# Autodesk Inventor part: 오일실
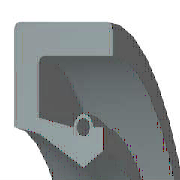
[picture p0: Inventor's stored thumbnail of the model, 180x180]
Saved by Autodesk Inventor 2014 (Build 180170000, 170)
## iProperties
IsCustomPart: 1
Created: 2015-12
Part Number: 오일실
Material: 일반
Description: 오일-실
Document SubType Name: Modeling
Standard: KS B 2804
Designer: mdu
Standards Organization: KS
Language: ko-KR
Size Designation: S - 15 30 7
Categories: <MemberInstance><Categories><Category DisplayName="샤프트 부품" InternalName="7f7aeb1f-a693-4053-b835-cee3144e0d98" Mnemonic="SHFT"><Category DisplayName="실링" Intern
Density: 1 g/cm^3
Appearance: 기본값
Mass: 1.76736 g
Surface Area: 26.6454 cm^2
Volume: 1.76736 cm^3
Author: mdu
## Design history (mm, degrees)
revolve "본체" stored, may be unused: angle "d17" = 90 deg
revolve "스프링1" stored, may be unused: angle "d18" = 90 deg
body "Solid1"
sketch "스케치1"
  geometry: L1 (0, 15)-(7, 15); L2 (7, 15)-(7, 13.75); L3 (7, 13.75)-(1.75, 13.75); L4 (0, 15)-(0, 9.6); L5 (0, 9.6)-(1.75, 9.25); L6 (1.75, 9.25)-(4.9, 7.5); L7 (4.9, 7.5)-(0, 7.5); L8 (6.3, 8.375)-(6.3, 9.6); L9 (0, 0)-(9.586, 0) reference; L10 (4.9, 7.5)-(6.3, 8.375); L11 (0, 18)-(0, -3) reference; L12 (-1.917, 0)-(11.503, 0) reference; L13 (4.2, 9.6)-(1.75, 10.09); L14 (1.75, 10.09)-(1.75, 13.75); L15 (6.3, 9.6)-(5.6, 9.6); C1 r 0.455 at (4.9, 9.6); A1 r 0.7 centre (4.9, 9.6) between (5.6, 9.6) and (4.2, 9.6)
  constraints: 26 end point, 5 horizontal alignment, 4 perpendicular, 2 centre point, 2 collinear, 2 horizontal, 2 parallel, 2 point on circle, 2 point on line, 2 vertical alignment, 1 coincident
  dimensions: "d0" = 30 diameter of L1 L9 (= SD2); "d1" = 16.75 diameter of L8.start L9 (= ABDM); "d2" = 1.25 distance of L1.end L2.end (computed from SD); "d3" = 0.91 diameter of C1 (= SPDI); "d4" = 1.4 diameter of A1 (= SPDA); "d5" = 15 diameter of L6.end L9 (= NND); "d6" = 18.5 diameter of L5.end L9 (= TKDM); "d7" = 19.2 diameter of L4.end L9 (= HLDM); "d8" = 4.9 distance from line of C1.centre L4 (= SPDST); "d9" = 6.3 distance between parallel lines of L8 L4 (= SDI); "d10" = 7 distance between parallel lines of L2 L4 (= SWDT); "d12" = 1.75 distance between parallel lines of L14 L4 (= SD)
fillet "모깎기1" dims "d11" = 0.3 (= RR)
other parameters: "SD2" = 30 [user parameter; used in 1 equation term], "SWDT" = 7 [user parameter; used in 1 equation term], "RR" = 0.3 [user parameter; used in 1 equation term], "SD" = 1.75 [user parameter; used in 2 equation terms], "NND" = 15 [user parameter; used in 1 equation term], "SPDA" = 1.4 [user parameter; used in 1 equation term], "SPDI" = 0.91 [user parameter; used in 1 equation term], "TKDM" = 18.5 [user parameter; used in 1 equation term], "HLDM" = 19.2 [user parameter; used in 1 equation term], "ABDM" = 16.75 [user parameter; used in 1 equation term], "SDI" = 6.3 [user parameter; used in 1 equation term], "SPDST" = 4.9 [user parameter; used in 1 equation term], "d13" = 0, "d14" = 0, "d15" = 0, "LAB" = 0.35 [user parameter]
